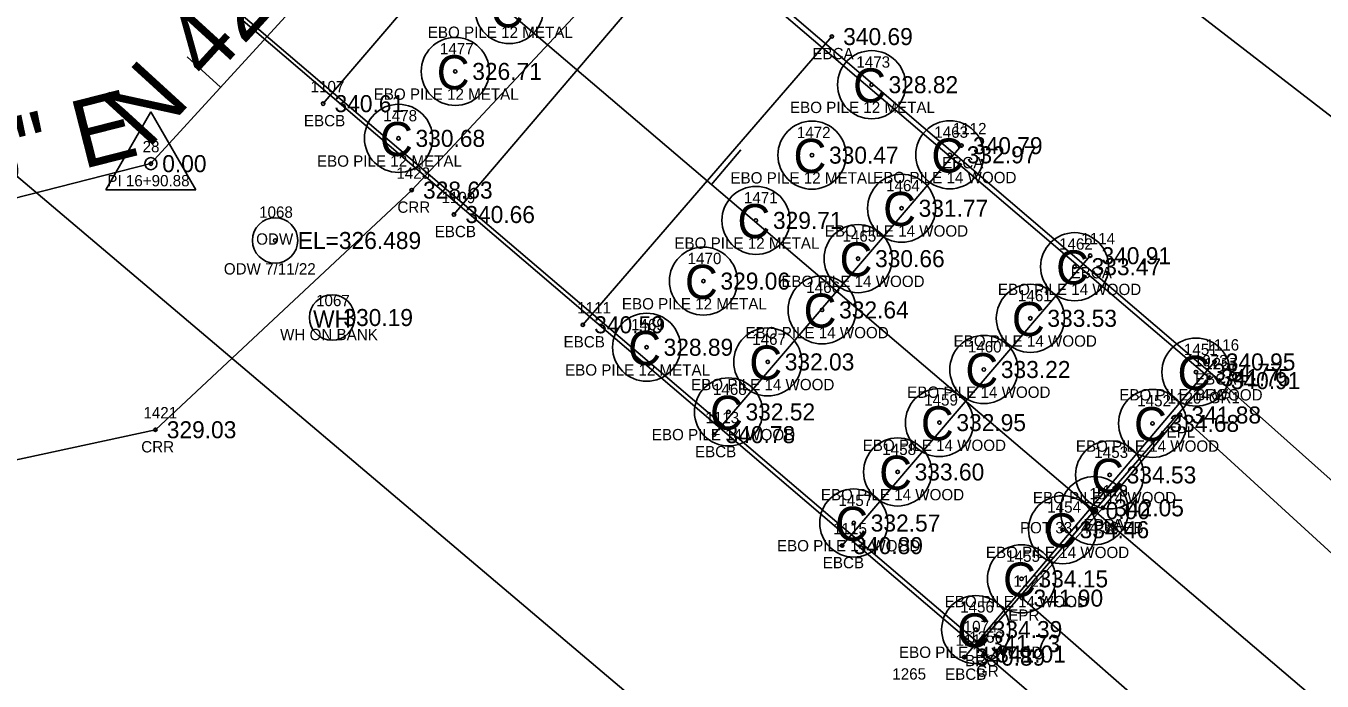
# Model space of a CAD drawing. Extents: x 2006517 to 2008868, y 1001613 to 1004633.
# Drawn here: x 2007831.6 to 2007945.8, y 1002865.2 to 1002922.9 of the extents above; entities that cross this region are included whole.
import ezdxf

# ---------------------------------------------------------------- set-up
doc = ezdxf.new("R2010")
doc.units = 0
for name, color, linetype in [('RD_EX_Bridge', 7, 'Continuous'), ('RD_EX_Bridge_txCode', 7, 'Continuous'), ('RD_EX_Fence_Other_txCode', 7, 'Continuous'), ('RD_EX_GuardRail', 7, 'Continuous'), ('RD_EX_GuardRail_txCode', 7, 'Continuous'), ('RD_EX_H2O', 7, 'Continuous'), ('RD_EX_H2O_txCode', 7, 'Continuous'), ('RD_EX_Road', 7, 'Continuous'), ('RD_EX_Road_txCode', 7, 'Continuous'), ('RD_EX_TX_Bridge_ELEV', 7, 'Continuous'), ('RD_EX_TX_GuardRail_ELEV', 7, 'Continuous'), ('RD_EX_TX_H2O_ELEV', 7, 'Continuous'), ('RD_EX_TX_Road_ELEV', 7, 'Continuous'), ('RD_EX_VEG', 7, 'Continuous'), ('RD_HC_Cl', 7, 'Continuous'), ('RD_HC_Data', 7, 'Continuous'), ('RD_HC_Data_Tic', 7, 'Continuous'), ('RD_HC_Survey_ELEV', 7, 'Continuous'), ('RD_HC_txCode', 7, 'Continuous'), ('RD_SMD_Locator', 7, 'Continuous')]:
    doc.layers.add(name, color=color, linetype=linetype)

msp = doc.modelspace()

# ---------------------------------------------------------------- linework, layer by layer
at = {"layer": 'RD_EX_Bridge'}
for p, q in [((2007879.51, 1002941.54), (2007857.79, 1002916.08)), ((2007891.06, 1002931.83), (2007869.32, 1002906.31)), ((2007902.63, 1002921.99), (2007880.68, 1002896.59)), ((2007914.07, 1002912.38), (2007892.26, 1002886.91)), ((2007925.4, 1002902.68), (2007903.53, 1002877.13)), ((2007936.36, 1002893.32), (2007914.31, 1002867.3))]:
    msp.add_line(p, q, dxfattribs=at)
msp.add_lwpolyline([(2007687.31, 1003063.05), (2007707.28, 1003086.65), (2007780.18, 1003024.5), (2007853.73, 1002962.01), (2007935.92, 1002891.93), (2007915.63, 1002868.5), (2007835.4, 1002936.88), (2007761.92, 1002999.52), (2007687.36, 1003063.04)], dxfattribs=at)
for centre in [(2007874.19, 1002924.37), (2007869.43, 1002918.92), (2007906.13, 1002917.75), (2007864.43, 1002913.02), (2007900.88, 1002911.54), (2007913.03, 1002911.57), (2007908.78, 1002906.86), (2007895.94, 1002905.79), (2007904.94, 1002902.42), (2007924.03, 1002901.71), (2007891.31, 1002900.44), (2007901.77, 1002897.9), (2007920.13, 1002897.16), (2007886.3, 1002894.61), (2007896.98, 1002893.32), (2007916.03, 1002892.65), (2007934.73, 1002892.42), (2007893.52, 1002888.91), (2007912.11, 1002887.97), (2007930.9, 1002887.9), (2007908.43, 1002883.62), (2007927.12, 1002883.36), (2007904.56, 1002879.12), (2007922.97, 1002878.53), (2007919.35, 1002874.2), (2007915.31, 1002869.73)]:
    msp.add_circle(centre, 3, dxfattribs=at)
at = {"layer": 'RD_EX_GuardRail'}
for points in [[(2007643.64, 1003141.95), (2007706.71, 1003087.87), (2007781.32, 1003024.2), (2007854.58, 1002961.97), (2007936.8, 1002891.67), (2008015.14, 1002821.85)], [(2007623.33, 1003114.9), (2007686.46, 1003063.73), (2007759.92, 1003000.81), (2007833.42, 1002938.17), (2007916.12, 1002867.57), (2007997.28, 1002798.14)]]:
    msp.add_lwpolyline(points, dxfattribs=at)
at = {"layer": 'RD_EX_H2O'}
msp.add_lwpolyline([(2007669.06, 1002953.29), (2007739.37, 1002899.33), (2007777.17, 1002873.15), (2007843, 1002887.34), (2007865.59, 1002908.46), (2007889.4, 1002933.96), (2007902.62, 1002951.59), (2007899.23, 1002956.7), (2007961.45, 1003046.31), (2007979.35, 1003079.78), (2008004.37, 1003099.33), (2008040.91, 1003092.79), (2008074.17, 1003079.43), (2008125.54, 1003053.8), (2008176.9, 1003027.12), (2008276.14, 1003020.76), (2008327.51, 1003029.06)], dxfattribs=at)
for centre, radius in [((2007853.55, 1002904.02), 2), ((2007853.55, 1002904.02), 0.15), ((2007858.57, 1002897.23), 2), ((2007858.57, 1002897.23), 0.005)]:
    msp.add_circle(centre, radius, dxfattribs=at)
at = {"layer": 'RD_EX_Road'}
for points in [[(2007926.53, 1002880.46), (2007933.33, 1002888.64), (2008004.37, 1002823.78), (2008041.16, 1002791.39), (2008076.97, 1002755.85), (2008109.64, 1002720.02), (2008140.82, 1002682.03), (2008169.79, 1002642.37), (2008196.81, 1002603.48), (2008249.05, 1002522.64), (2008259.94, 1002505.27), (2008271.29, 1002488.2), (2008299.71, 1002443.6), (2008349.96, 1002366.27), (2008401.09, 1002286.99), (2008453.35, 1002207.39), (2008504.32, 1002128.41), (2008557.14, 1002047.24), (2008604.7, 1001974.22), (2008628.71, 1001937.76), (2008659.22, 1001891.69), (2008712.34, 1001810.72), (2008764.8, 1001729.24), (2008801.79, 1001664.14)], [(2007926.53, 1002880.46), (2007919.41, 1002872.5), (2007991.54, 1002809.35), (2008026.83, 1002776.85), (2008062.37, 1002741.51), (2008093.99, 1002707.06), (2008125.02, 1002669.01), (2008154.41, 1002630.27), (2008179.59, 1002592.85), (2008187.94, 1002580.41), (2008232, 1002511.78), (2008283.05, 1002433.59)]]:
    msp.add_lwpolyline(points, dxfattribs=at)
at = {"layer": 'RD_EX_VEG'}
for points in [[(2007395.89, 1003327.12), (2007429.8, 1003285.17), (2007467.04, 1003247.92), (2007498.61, 1003210.85), (2007670.4, 1003045.37), (2007967.56, 1002793.96), (2008054.61, 1002736.66), (2008078.76, 1002693.39), (2008113.28, 1002661.09), (2008135.36, 1002619.06), (2008159.5, 1002583.06), (2008222.5, 1002503.36), (2008272.84, 1002426.91), (2008323.43, 1002347.7), (2008431.42, 1002192), (2008479.95, 1002108.23), (2008533.09, 1002033.28), (2008631.97, 1001873.89), (2008775.08, 1001653.06)], [(2007473.93, 1003322.69), (2007503.07, 1003282.99), (2007540.25, 1003252.05), (2007579.27, 1003219.13), (2007642.18, 1003150.48), (2007952.5, 1002910.4), (2008017.59, 1002836.73), (2008047.98, 1002799.05), (2008087.42, 1002767.09), (2008121.48, 1002729.06), (2008151.49, 1002690.42), (2008185.86, 1002650.76), (2008208.76, 1002609.15), (2008254.04, 1002533.01), (2008311.38, 1002450.28), (2008360.35, 1002372.97), (2008409.06, 1002292.02), (2008460.63, 1002215.28), (2008512.48, 1002133.62), (2008564.88, 1002053.16), (2008614.62, 1001980.71), (2008661.43, 1001938.2)]]:
    msp.add_lwpolyline(points, dxfattribs=at)
at = {"layer": 'RD_HC_Cl'}
for p, q in [((2007559.77, 1003192.01), (2007994.36, 1002821.78)), ((2007842.6, 1002910.79), (2007883.99, 1002956.11)), ((2007793.45, 1002898.27), (2007842.6, 1002910.79))]:
    msp.add_line(p, q, dxfattribs=at)
at = {"layer": 'RD_HC_Data'}
for p, q in [((2007838.63, 1002908.49), (2007842.6, 1002915.37)), ((2007842.6, 1002915.37), (2007846.57, 1002908.49)), ((2007838.63, 1002908.49), (2007846.57, 1002908.49))]:
    msp.add_line(p, q, dxfattribs=at)
for centre, radius in [((2007842.6, 1002910.79), 0.529), ((2007925.77, 1002880.21), 3), ((2007925.77, 1002880.21), 0.282)]:
    msp.add_circle(centre, radius, dxfattribs=at)
at = {"layer": 'RD_HC_Data_Tic'}
for p, q in [((2007848.75, 1002917.52), (2007845.79, 1002920.21)), ((2007892.03, 1002908.96), (2007894.62, 1002912.01))]:
    msp.add_line(p, q, dxfattribs=at)
at = {"layer": 'RD_SMD_Locator'}
for centre in [(2007902.63, 1002921.99), (2007869.43, 1002918.92), (2007906.13, 1002917.75), (2007857.79, 1002916.08), (2007864.43, 1002913.02), (2007900.88, 1002911.54), (2007913.03, 1002911.57), (2007914.07, 1002912.38), (2007842.6, 1002910.79), (2007865.59, 1002908.46), (2007908.78, 1002906.86), (2007869.32, 1002906.31), (2007895.94, 1002905.79), (2007904.94, 1002902.42), (2007925.4, 1002902.68), (2007924.03, 1002901.71), (2007891.31, 1002900.44), (2007901.77, 1002897.9), (2007880.68, 1002896.59), (2007920.13, 1002897.16), (2007886.3, 1002894.61), (2007896.98, 1002893.32), (2007936.36, 1002893.32), (2007916.03, 1002892.65), (2007934.73, 1002892.42), (2007935.92, 1002891.93), (2007936.8, 1002891.67), (2007893.52, 1002888.91), (2007933.33, 1002888.64), (2007912.11, 1002887.97), (2007930.9, 1002887.9), (2007843, 1002887.34), (2007892.26, 1002886.91), (2007908.43, 1002883.62), (2007927.12, 1002883.36), (2007925.77, 1002880.21), (2007926.53, 1002880.46), (2007926.53, 1002880.46), (2007904.56, 1002879.12), (2007922.97, 1002878.53), (2007903.53, 1002877.13), (2007919.35, 1002874.2), (2007919.41, 1002872.5), (2007915.31, 1002869.73), (2007915.63, 1002868.5), (2007914.31, 1002867.3), (2007916.12, 1002867.57)]:
    msp.add_circle(centre, 0.15, dxfattribs=at)

# ---------------------------------------------------------------- texts
at = {"layer": 'RD_EX_Bridge'}
for p in [(2007872.56, 1002922.8), (2007867.8, 1002917.35), (2007904.5, 1002916.19), (2007862.8, 1002911.46), (2007899.25, 1002909.98), (2007911.4, 1002910.01), (2007907.15, 1002905.3), (2007894.31, 1002904.23), (2007903.31, 1002900.86), (2007922.4, 1002900.15), (2007889.68, 1002898.88), (2007900.14, 1002896.34), (2007918.5, 1002895.6), (2007884.67, 1002893.05), (2007895.35, 1002891.76), (2007914.4, 1002891.09), (2007933.1, 1002890.86), (2007891.89, 1002887.34), (2007910.48, 1002886.41), (2007929.27, 1002886.34), (2007906.8, 1002882.06), (2007925.49, 1002881.79), (2007902.93, 1002877.56), (2007921.34, 1002876.97), (2007917.72, 1002872.64), (2007913.68, 1002868.16)]:
    msp.add_text('C', height=3, dxfattribs=at).set_placement(p)
at = {"layer": 'RD_EX_Bridge_txCode'}
for s, p in [('EBO PILE 12 METAL', (2007867.01, 1002921.87)), ('1477', (2007868.08, 1002920.42)), ('EBCA', (2007900.91, 1002919.99)), ('1473', (2007904.79, 1002919.25)), ('1107', (2007856.68, 1002917.08)), ('EBO PILE 12 METAL', (2007862.24, 1002916.42)), ('EBO PILE 12 METAL', (2007898.94, 1002915.25)), ('EBCB', (2007856.09, 1002914.08)), ('1478', (2007863.09, 1002914.52)), ('1472', (2007899.54, 1002913.04)), ('1463', (2007911.66, 1002913.07)), ('1112', (2007913.29, 1002913.38)), ('EBO PILE 12 METAL', (2007857.24, 1002910.52)), ('EBCA', (2007912.35, 1002910.38)), ('EBO PILE 12 METAL', (2007893.69, 1002909.04)), ('EBO PILE 14 WOOD', (2007906.27, 1002909.07)), ('1464', (2007907.41, 1002908.36)), ('1109', (2007868.22, 1002907.31)), ('1471', (2007894.88, 1002907.29)), ('EBCB', (2007867.62, 1002904.31)), ('EBO PILE 14 WOOD', (2007902.01, 1002904.36)), ('1465', (2007903.57, 1002903.92)), ('1114', (2007924.62, 1002903.68)), ('EBO PILE 12 METAL', (2007888.75, 1002903.29)), ('1462', (2007922.66, 1002903.21)), ('1470', (2007889.92, 1002901.94)), ('EBCA', (2007923.68, 1002900.68)), ('EBO PILE 14 WOOD', (2007898.17, 1002899.92)), ('1466', (2007900.38, 1002899.4)), ('EBO PILE 14 WOOD', (2007917.27, 1002899.21)), ('EBO PILE 12 METAL', (2007884.12, 1002897.94)), ('1461', (2007919.04, 1002898.66)), ('1111', (2007880.18, 1002897.59)), ('1469', (2007884.93, 1002896.11)), ('EBCB', (2007878.98, 1002894.59)), ('EBO PILE 14 WOOD', (2007895.01, 1002895.4)), ('1467', (2007895.61, 1002894.82)), ('EBO PILE 14 WOOD', (2007913.36, 1002894.66)), ('1460', (2007914.62, 1002894.15)), ('1451', (2007933.67, 1002893.92)), ('1116', (2007935.56, 1002894.32)), ('1073', (2007934.54, 1002892.93)), ('EBO PILE 12 METAL', (2007879.11, 1002892.11)), ('EBCA', (2007934.64, 1002891.32)), ('EBO PILE 14 WOOD', (2007890.22, 1002890.82)), ('1468', (2007892.15, 1002890.41)), ('EBO PILE 14 WOOD', (2007909.27, 1002890.15)), ('EBO PILE 14 WOOD', (2007927.97, 1002889.92)), ('BRC', (2007934.67, 1002889.93)), ('1459', (2007910.77, 1002889.47)), ('1452', (2007929.55, 1002889.4)), ('1113', (2007891.48, 1002887.91)), ('EBO PILE 14 WOOD', (2007886.76, 1002886.41)), ('EBO PILE 14 WOOD', (2007905.35, 1002885.47)), ('EBO PILE 14 WOOD', (2007924.14, 1002885.4)), ('EBCB', (2007890.56, 1002884.91)), ('1458', (2007907.08, 1002885.12)), ('1453', (2007925.77, 1002884.86)), ('EBO PILE 14 WOOD', (2007901.66, 1002881.12)), ('EBO PILE 14 WOOD', (2007920.35, 1002880.86)), ('1457', (2007903.21, 1002880.62)), ('1454', (2007921.62, 1002880.03)), ('1115', (2007902.75, 1002878.13)), ('EBO PILE 14 WOOD', (2007897.79, 1002876.62)), ('EBCB', (2007901.83, 1002875.13)), ('EBO PILE 14 WOOD', (2007916.21, 1002876.03)), ('1455', (2007918, 1002875.7)), ('EBO PILE 14 WOOD', (2007912.58, 1002871.7)), ('1456', (2007913.94, 1002871.23)), ('1074', (2007914.25, 1002869.5)), ('1117', (2007913.53, 1002868.3)), ('EBO PILE 14 WOOD', (2007908.55, 1002867.23)), ('BRC', (2007914.38, 1002866.5)), ('EBCB', (2007912.61, 1002865.3))]:
    msp.add_text(s, height=1, dxfattribs=at).set_placement(p)
at = {"layer": 'RD_EX_Fence_Other_txCode'}
msp.add_text('1265', height=1, dxfattribs=at).set_placement((2007907.96, 1002865.32))
at = {"layer": 'RD_EX_GuardRail_txCode'}
for s, p in [('1257', (2007935.45, 1002892.67)), ('GR1', (2007935.85, 1002889.67)), ('1256', (2007914.75, 1002868.57)), ('GR', (2007915.34, 1002865.57))]:
    msp.add_text(s, height=1, dxfattribs=at).set_placement(p)
at = {"layer": 'RD_EX_H2O'}
for s, height, p in [('ODW', 1, (2007851.88, 1002903.65)), ('WH', 1.5, (2007856.9, 1002896.35))]:
    msp.add_text(s, height=height, dxfattribs=at).set_placement(p)
at = {"layer": 'RD_EX_H2O_txCode'}
for s, p in [('1423', (2007864.24, 1002909.46)), ('1068', (2007852.14, 1002906.02)), ('CRR', (2007864.33, 1002906.46)), ('ODW 7/11/22', (2007849.03, 1002901.02)), ('1067', (2007857.16, 1002898.23)), ('WH ON BANK', (2007853.99, 1002895.23)), ('1421', (2007841.94, 1002888.34)), ('CRR', (2007841.75, 1002885.34))]:
    msp.add_text(s, height=1, dxfattribs=at).set_placement(p)
at = {"layer": 'RD_EX_Road_txCode'}
for s, p in [('1120', (2007932.23, 1002889.64)), ('EPL', (2007932.13, 1002886.64)), ('1118', (2007925.75, 1002881.46)), ('1119', (2007925.75, 1002881.46)), ('EPRA', (2007924.82, 1002878.46)), ('EPLA', (2007924.84, 1002878.46)), ('1121', (2007918.63, 1002873.5)), ('EPR', (2007918.18, 1002870.5))]:
    msp.add_text(s, height=1, dxfattribs=at).set_placement(p)
at = {"layer": 'RD_EX_TX_Bridge_ELEV'}
for s, p in [('340.69', (2007903.63, 1002921.24)), ('326.71', (2007870.93, 1002918.17)), ('328.82', (2007907.63, 1002917)), ('340.61', (2007858.79, 1002915.33)), ('330.68', (2007865.93, 1002912.27)), ('340.79', (2007915.07, 1002911.63)), ('330.47', (2007902.38, 1002910.79)), ('332.97', (2007914.53, 1002910.82)), ('340.66', (2007870.32, 1002905.56)), ('331.77', (2007910.28, 1002906.11)), ('329.71', (2007897.44, 1002905.04)), ('330.66', (2007906.44, 1002901.67)), ('333.47', (2007925.53, 1002900.96)), ('340.91', (2007926.4, 1002901.93)), ('329.06', (2007892.81, 1002899.69)), ('332.64', (2007903.27, 1002897.15)), ('333.53', (2007921.63, 1002896.41)), ('340.59', (2007881.68, 1002895.84)), ('328.89', (2007887.8, 1002893.86)), ('332.03', (2007898.48, 1002892.57)), ('333.22', (2007917.53, 1002891.9)), ('340.95', (2007937.36, 1002892.57)), ('334.77', (2007936.23, 1002891.67)), ('341.75', (2007936.92, 1002891.18)), ('332.52', (2007895.02, 1002888.16)), ('332.95', (2007913.61, 1002887.22)), ('334.68', (2007932.4, 1002887.15)), ('340.78', (2007893.26, 1002886.16)), ('333.60', (2007909.93, 1002882.87)), ('334.53', (2007928.62, 1002882.61)), ('332.57', (2007906.06, 1002878.37)), ('334.46', (2007924.47, 1002877.78)), ('340.89', (2007904.53, 1002876.38)), ('334.15', (2007920.85, 1002873.45)), ('334.39', (2007916.81, 1002868.98)), ('341.73', (2007916.63, 1002867.75)), ('340.89', (2007915.31, 1002866.55))]:
    msp.add_text(s, height=1.5, dxfattribs=at).set_placement(p)
at = {"layer": 'RD_EX_TX_GuardRail_ELEV'}
for s, p in [('340.91', (2007937.8, 1002890.92)), ('341.01', (2007917.12, 1002866.82))]:
    msp.add_text(s, height=1.5, dxfattribs=at).set_placement(p)
at = {"layer": 'RD_EX_TX_H2O_ELEV'}
for s, p in [('328.63', (2007866.59, 1002907.71)), ('EL=326.489', (2007855.55, 1002903.27)), ('330.19', (2007859.57, 1002896.48)), ('329.03', (2007844, 1002886.59))]:
    msp.add_text(s, height=1.5, dxfattribs=at).set_placement(p)
at = {"layer": 'RD_EX_TX_Road_ELEV'}
for s, p in [('341.88', (2007934.33, 1002887.89)), ('342.05', (2007927.53, 1002879.71)), ('342.05', (2007927.53, 1002879.71)), ('341.90', (2007920.41, 1002871.75))]:
    msp.add_text(s, height=1.5, dxfattribs=at).set_placement(p)
at = {"layer": 'RD_HC_Data'}
for s, rotation, p in [('N 42%%d 23\' 58" E', 47.6006, (2007842.31, 1002911.95)), ('N 75%%d 42\' 35" E', 14.2902, (2007789, 1002898.17))]:
    msp.add_text(s, height=6, rotation=rotation, dxfattribs=at).set_placement(p)
at = {"layer": 'RD_HC_Survey_ELEV'}
for p in [(2007843.6, 1002910.04), (2007926.77, 1002879.46)]:
    msp.add_text('0.00', height=1.5, dxfattribs=at).set_placement(p)
at = {"layer": 'RD_HC_txCode'}
for s, p in [('28', (2007841.87, 1002911.79)), ('PI 16+90.88', (2007838.76, 1002908.79)), ('15', (2007925.33, 1002881.21)), ('POT 33+44.33 EB', (2007919.21, 1002878.21))]:
    msp.add_text(s, height=1, dxfattribs=at).set_placement(p)

doc.saveas('drawing.dxf')
